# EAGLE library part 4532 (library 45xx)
8-bit PRIORITY ENCODER
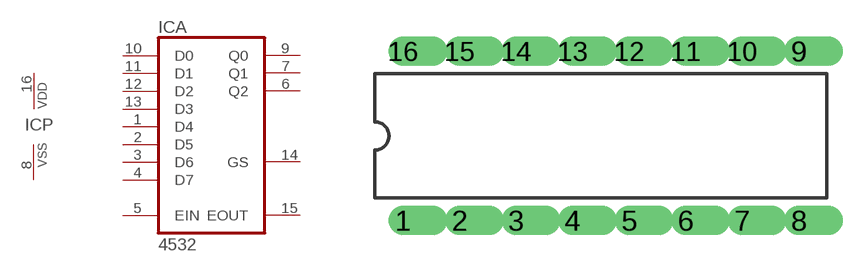
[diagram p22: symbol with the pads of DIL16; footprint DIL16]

Designator prefix IC; gates A=4532 P=PWRN

## 4532N  [DIL16]
1  A:D4  in
2  A:D5  in
3  A:D6  in
4  A:D7  in
5  A:EIN  in
6  A:Q2  out
7  A:Q1  out
8  P:VSS  pwr
9  A:Q0  out
10  A:D0  in
11  A:D1  in
12  A:D2  in
13  A:D3  in
14  A:GS  out
15  A:EOUT  out
16  P:VDD  pwr

## Footprint DIL16 (pad centres in mm)
Dual In Line
drill 0.813 offset: 1 -8.89,-3.81; 2 -6.35,-3.81; 3 -3.81,-3.81; 4 -1.27,-3.81; 5 1.27,-3.81; 6 3.81,-3.81; 7 6.35,-3.81; 8 8.89,-3.81; 9 8.89,3.81; 10 6.35,3.81; 11 3.81,3.81; 12 1.27,3.81; 13 -1.27,3.81; 14 -3.81,3.81; 15 -6.35,3.81; 16 -8.89,3.81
